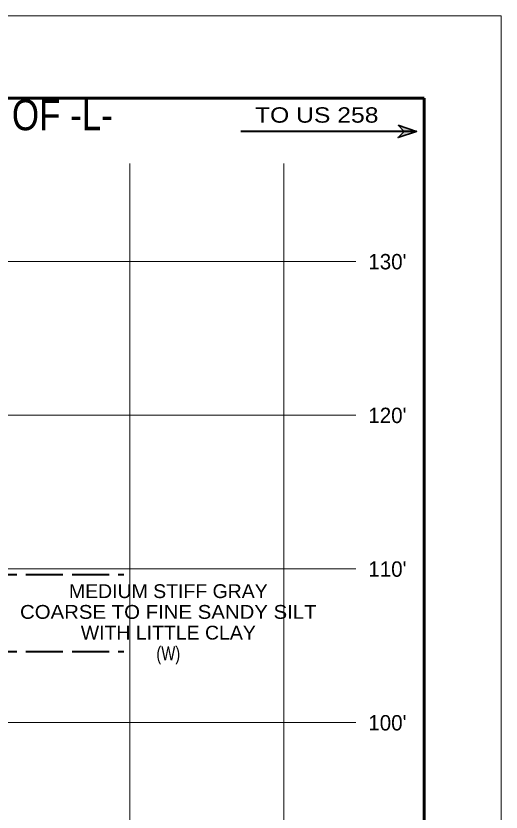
# Model space of a CAD drawing. Extents: x -582 to 653, y -817 to -3.
# Drawn here: x -133.2 to -101.6, y -211.3 to -159.5 of the extents above; entities that cross this region are included whole.
import ezdxf
from ezdxf.enums import TextEntityAlignment as Align

# ---------------------------------------------------------------- set-up
doc = ezdxf.new("R2010")
doc.units = 0
doc.header["$LTSCALE"] = 0.4
doc.linetypes.add('LONG_DASHED', pattern=[7.5, 6, -1.5])
for name, color, linetype, lineweight in [('10', 7, 'Continuous', 35), ('26', 7, 'LONG_DASHED', 40), ('27', 7, 'Continuous', 40), ('63', 7, 'Continuous', 35), ('7', 7, 'Continuous', 13)]:
    doc.layers.add(name, color=color, linetype=linetype, lineweight=lineweight)
doc.layers.add('29', color=7, linetype='Continuous')

msp = doc.modelspace()

# ---------------------------------------------------------------- hatches: boundary and pattern name
at = {"layer": '10'}
msp.add_hatch(color=256, dxfattribs=at).paths.add_polyline_path([(-108.3295, -166.6105), (-107.1295, -167.0105), (-108.3295, -167.4105), (-107.9295, -167.0105)])

# ---------------------------------------------------------------- linework, layer by layer
msp.add_lwpolyline([(-108.3295, -166.6105), (-107.1295, -167.0105), (-108.3295, -167.4105), (-107.9295, -167.0105)], close=True, dxfattribs=at)
at = {"layer": '26'}
for points in [[(-153.1592, -195.8305), (-144.783, -195.843), (-141.0156, -195.843), (-138.5156, -195.843), (-126.149, -195.843)], [(-153.1592, -200.8305), (-144.783, -200.843), (-141.0157, -200.8429), (-138.5156, -200.8429), (-126.1491, -200.8429)]]:
    msp.add_lwpolyline(points, dxfattribs=at)
at = {"layer": '27'}
msp.add_line((-107.1295, -167.0105), (-118.5513, -167.0142), dxfattribs=at)
at = {"layer": '63', "lineweight": 13}
for p in [(-211.6418, -159.4952), (-101.6418, -329.4952)]:
    msp.add_line(p, (-101.6418, -159.4952), dxfattribs=at)
at = {"layer": '63', "lineweight": 60}
for q in [(-206.6418, -164.8424), (-106.6418, -325.4952)]:
    msp.add_line((-106.6418, -164.8424), q, dxfattribs=at)
at = {"layer": '7'}
for p, q in [((-125.7656, -315.4816), (-125.7656, -169.1034)), ((-115.7656, -315.4816), (-115.7656, -169.1034)), ((-202.3744, -175.4729), (-111.0807, -175.4729)), ((-202.3744, -185.4729), (-111.0807, -185.4729)), ((-134.3937, -195.4729), (-111.0807, -195.4729)), ((-134.7405, -205.4729), (-111.0807, -205.4729))]:
    msp.add_line(p, q, dxfattribs=at)

# ---------------------------------------------------------------- texts
at = {"layer": '27', "width": 1.2}
msp.add_text('TO US 258', height=1, dxfattribs=at).set_placement((-113.6228, -166.4403), align=Align.CENTER)
at = {"layer": '29'}
for s, width, p in [('MEDIUM STIFF GRAY', 1.05, (-123.2671, -197.3707)), ('COARSE TO FINE SANDY SILT', 1.1, (-123.2671, -198.7207)), ('WITH LITTLE CLAY', 1.05, (-123.2671, -200.0707)), ('(W)', 0.8, (-123.2671, -201.4207))]:
    msp.add_text(s, height=0.9, dxfattribs=dict(at, width=width)).set_placement(p, align=Align.CENTER)
at = {"layer": '63', "width": 0.85}
msp.add_text("GENERALIZED SUBSURFACE PROFILE 35' LEFT OF -L-", height=2, dxfattribs=at).set_placement((-156.6418, -166.9305), align=Align.CENTER)
at = {"layer": '63'}
for s, p in [("130'", (-109.0275, -175.9837)), ("120'", (-109.0275, -185.9837)), ("110'", (-109.0273, -195.9837)), ("100'", (-109.0275, -205.9837))]:
    msp.add_text(s, height=1, dxfattribs=at).set_placement(p, align=Align.CENTER)

doc.saveas('drawing.dxf')
